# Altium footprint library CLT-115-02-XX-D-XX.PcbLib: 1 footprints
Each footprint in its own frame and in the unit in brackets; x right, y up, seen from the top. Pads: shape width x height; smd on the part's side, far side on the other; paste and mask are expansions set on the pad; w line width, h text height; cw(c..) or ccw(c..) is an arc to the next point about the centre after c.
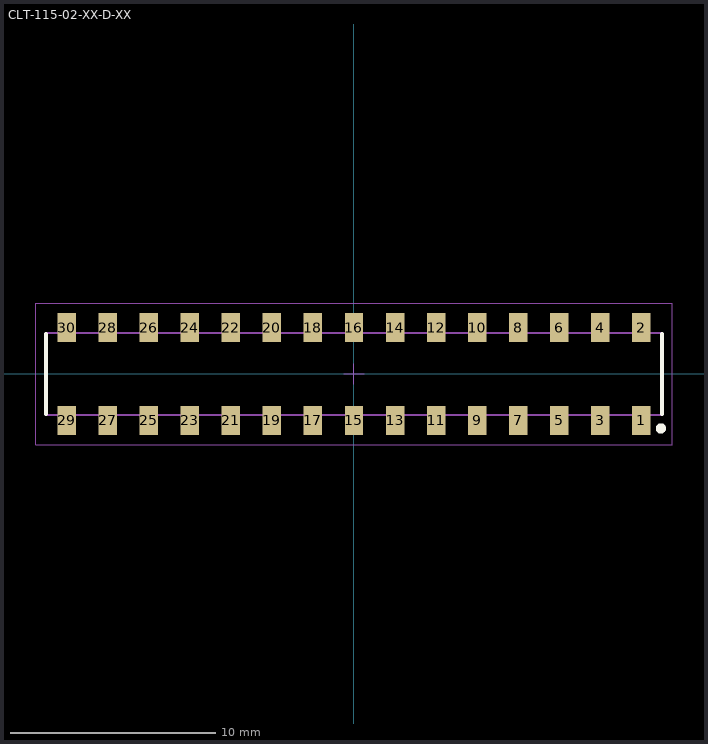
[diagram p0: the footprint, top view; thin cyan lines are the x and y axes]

## CLT-115-02-XX-D-XX [mm] "2.00mm pitch, 30 pin, socket strip; low profile"
height 2.13
pads (30):
  rect 0.9x1.4 smd mask+0: 1(13.993,-2.261) 2(13.993,2.261) 3(11.994,-2.261) 4(11.994,2.261) 5(9.995,-2.261) 6(9.995,2.261) 7(7.996,-2.261) 8(7.996,2.261) 9(5.997,-2.261) 10(5.997,2.261) 11(3.998,-2.261) 12(3.998,2.261) 13(1.999,-2.261) 14(1.999,2.261) 15(0,-2.261) 16(0,2.261) 17(-1.999,-2.261) 18(-1.999,2.261) 19(-3.998,-2.261) 20(-3.998,2.261) 21(-5.997,-2.261) 22(-5.997,2.261) 23(-7.996,-2.261) 24(-7.996,2.261) 25(-9.995,-2.261) 26(-9.995,2.261) 27(-11.994,-2.261) 28(-11.994,2.261) 29(-13.993,-2.261) 30(-13.993,2.261)
Top Overlay:
  circle w0.25: c14.95,-2.65 r0.125
  lines w0.2: -15,-1.95 -15,1.95 ; 15,-1.95 15,1.95
Mechanical 12:
  lines w0.001: -15,-2 -15,2 15,2 15,-2 -15,-2
Mechanical 13:
  lines w0.1: -15,-2 -15,2 15,2 15,-2 -15,-2
  text ".Designator" at 0.254,0.254 h1.52
Mechanical 15:
  lines w0.05: -0.5,0 0.5,0 ; 0,-0.5 0,0.5 ; -15.5,-3.45 -15.5,3.45 15.5,3.45 15.5,-3.45 -15.5,-3.45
